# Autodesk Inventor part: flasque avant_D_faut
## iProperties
Created: 2011-10
Part Number: flasque avant_D_faut
Document SubType Name: Modeling
Designer: Bruno
Author: Bruno
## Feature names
1. Base1
